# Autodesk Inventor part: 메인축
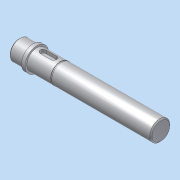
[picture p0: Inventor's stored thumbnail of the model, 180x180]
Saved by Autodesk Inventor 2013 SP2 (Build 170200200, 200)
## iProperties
Company: 한국ATC센터
Created: 2014-12
Part Number: 메인축
Document SubType Name: Modeling
Designer: KYOUNG IL JANG
Density: 1 g/cm^3
Mass: 27.2374 g
Surface Area: 71.2962 cm^2
Volume: 27.2374 cm^3
Material: 일반
Author: KYOUNG IL JANG
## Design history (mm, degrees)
sketch "스케치1"
  geometry: L1 (0, 0)-(120, 0); L2 (0, 0)-(0, 7.5); L3 (1, 8.5)-(12, 8.5); L4 (12, 8.5)-(12, 10); L5 (12, 10)-(15, 10); L6 (15, 10)-(15, 8.5); L7 (15, 8.5)-(119, 8.5); L8 (120, 0)-(120, 7.5); L9 (1, 8.5)-(0, 7.5); L10 (119, 8.5)-(120, 7.5); 2 further points
  constraints: 20 end point, 4 point on line, 3 parallel, 3 perpendicular, 1 collinear, 1 horizontal
  dimensions: "d0" = 12 distance of point (0, 8.5) L3.end; "d1" = 17 diameter of L3 L1; "d2" = 20 diameter of L5 L1; "d3" = 17 diameter of L7 L1; "d4" = 3 distance of L4.end L5.end; "d5" = 120 distance of L1.start L1.end; "d6" = 1 distance of L3.start point (0, 8.5); "d7" = 1 distance of L2.end point (0, 8.5) (= d6); "d8" = 1 distance of L7.end point (120, 8.5) (= d6); "d9" = 1 distance of L8.end point (120, 8.5) (= d8)
revolve "회전1" sketch "스케치1" stored, may be unused: angle "d10" = 90 deg
node "작업 평면1"
sketch "스케치2"
  geometry: L1 (-46.5, 2.5)-(-37.5, 2.5); L2 (-37.5, -2.5)-(-46.5, -2.5); L3 (-52, -10)-(-52, 10) reference; A1 r 2.5 centre (-37.5, 0) between (-37.5, -2.5) and (-37.5, 2.5); A2 r 2.5 centre (-46.5, 0) between (-46.5, 2.5) and (-46.5, -2.5); 1 further point
  constraints: 4 end point, 4 point on circle, 4 tangent, 2 centre point, 1 horizontal, 1 horizontal alignment, 1 parallel
  dimensions: "d11" = 5 distance between parallel lines of L2 L1; "d12" = 3 distance edge to line of A2 L3; "d13" = 14 dimension on A1 A2
extrude "돌출1" cut sketch "스케치2" distance "d14" = 3; taper "d15" = 0 deg
sketch "스케치3"
  geometry: L1 (15, 8.5)-(119, 8.5) reference; L2 (35, 8.5)-(36.15, 8.5); L3 (36.15, 8.5)-(36.15, 8.1); L4 (36.15, 8.1)-(35, 8.1); L5 (35, 8.1)-(35, 8.5); L6 (15, -10)-(15, 10) reference; L7 (-23.8, 0)-(142.8, 0) reference; 1 further point
  constraints: 8 end point, 2 parallel, 1 horizontal, 1 perpendicular, 1 point on line
  dimensions: "d16" = 1.15 distance of L3.end L4.end; "d17" = 20 distance between parallel lines of L5 L6; "d18" = 8.1 distance from line of L4 point (0, 0)
revolve "회전2" sketch "스케치3" stored, may be unused: angle "d19" = 90 deg
node "솔리드1"
